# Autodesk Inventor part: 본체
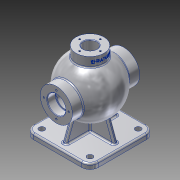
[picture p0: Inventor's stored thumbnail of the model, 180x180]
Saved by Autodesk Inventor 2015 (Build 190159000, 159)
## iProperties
Created: 2025-08
Part Number: 본체
Material: 알루미늄 6061
Document SubType Name: Modeling
Designer: USER
Density: 2.7 g/cm^3
Appearance: 알루미늄 - 평지
Author: USER
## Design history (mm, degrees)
sketch "스케치2"
  geometry: L1 (-46.5, -62.5)-(46.5, -62.5); L2 (62.5, -46.5)-(62.5, 46.5); L3 (46.5, 62.5)-(-46.5, 62.5); L4 (-62.5, 46.5)-(-62.5, -46.5); L5 (-62.5, -62.5)-(62.5, 62.5); L6 (62.5, -62.5)-(-62.5, 62.5); A1 r 16 centre (-46.5, 46.5) between (-46.5, 62.5) and (-62.5, 46.5); A2 r 16 centre (46.5, 46.5) between (62.5, 46.5) and (46.5, 62.5); A3 r 16 centre (46.5, -46.5) between (46.5, -62.5) and (62.5, -46.5); A4 r 16 centre (-46.5, -46.5) between (-62.5, -46.5) and (-46.5, -62.5); 1 further point
  constraints: 12 end point, 8 point on circle, 8 point on line, 8 tangent, 4 centre point, 3 equal radius, 2 midpoint, 2 parallel, 1 horizontal, 1 perpendicular
  dimensions: "d0" = 125 distance of L6.end L5.end; "d1" = 125 distance of L5.end L6.start; "d4" = 16 radius of A1
extrude "돌출1" new body sketch "스케치2" distance "d2" = 10; taper "d3" = 0 deg
sketch "스케치6"
  geometry: L1 (-46.5, 0)-(46.5, 0) reference; L2 (0, 139)-(0, 31); A1 r 54 centre (0, 85) between (0, 139) and (0, 31); 3 further points
  constraints: 2 end point, 2 midpoint, 2 point on circle, 1 centre point, 1 coincident, 1 vertical, 1 vertical alignment
  dimensions: "d20" = 108 diameter of A1; "d21" = 85 distance from line of A1.centre L1
revolve "회전1" sketch "스케치6" stored, may be unused: angle "d22" = 90 deg
node "작업 평면1"
sketch "스케치7"
  geometry: C1 r 27 at (0, 0); 1 further point
  constraints: 1 centre point, 1 coincident
  dimensions: "d24" = 54 diameter of C1
extrude "돌출2" join sketch "스케치7" stored distance "d25" = 10; taper "d26" = 0 deg
node "작업 평면2"
sketch "스케치8"
  geometry: C1 r 31 at (0, 83); 1 further point
  constraints: 1 centre point, 1 vertical alignment
  dimensions: "d28" = 62 diameter of C1; "d29" = 83 distance of point (0, 0) C1.centre
extrude "돌출3" join sketch "스케치8" distance "d30" = 130; taper "d31" = 0 deg
sketch "스케치9"
  geometry: L1 (-4, -50.5)-(4, -50.5); L2 (4, -50.5)-(4, 50.5); L3 (4, 50.5)-(-4, 50.5); L4 (-4, 50.5)-(-4, -50.5); L5 (-4, -50.5)-(4, 50.5); L6 (4, -50.5)-(-4, 50.5); L7 (-50.5, -4)-(50.5, -4); L8 (50.5, -4)-(50.5, 4); L9 (50.5, 4)-(-50.5, 4); L10 (-50.5, 4)-(-50.5, -4); L11 (-50.5, -4)-(50.5, 4); L12 (50.5, -4)-(-50.5, 4); L13 (-46.5, 62.5)-(46.5, 62.5) reference; L14 (62.5, 46.5)-(62.5, -46.5) reference; 1 further point
  constraints: 24 end point, 4 midpoint, 4 parallel, 2 horizontal, 2 perpendicular
  dimensions: "d32" = 8 distance of L2.end L3.end; "d33" = 8 distance of L7.end L8.end; "d34" = 12 distance between parallel lines of L3 L13; "d35" = 12 distance between parallel lines of L8 L14
extrude "돌출4" join sketch "스케치9" distance "d36" = 85; taper "d37" = 0 deg
feature "면 기울기1" dims angle "d38" = 20 deg
hole "구멍1" diameter "d41" = 26; stored, may be unused: countersink angle "d45" = 90 deg, drill point angle "d47" = 0 deg; dims "d39" = 10, "d40" = 10, "d42" = 6, "d43" = 4, "d44" = 2, "d46" = 100
hole "구멍2" diameter "d50" = 30; stored, may be unused: countersink angle "d54" = 90 deg, drill point angle "d56" = 0 deg; dims "d48" = 10, "d49" = 10, "d51" = 6, "d52" = 35, "d53" = 16, "d55" = 100
sketch "스케치10"
  geometry: L1 (-27, 131.765)-(-27, 150) reference; L2 (-27, 150)-(-13, 150) reference; L3 (-13, 150)-(-13, 98) reference; L4 (-13, 98)-(-49, 98) reference; L5 (-49, 98)-(-49, 100.5) reference; L6 (-49, 100.5)-(-65, 100.5) reference; L7 (-65, 100.5)-(-65, 114) reference; L8 (-65, 114)-(-45.552, 114) reference; L9 (45.552, 114)-(65, 114) reference; L10 (65, 114)-(65, 100.5) reference; L11 (65, 100.5)-(49, 100.5) reference; L12 (49, 100.5)-(49, 98) reference; L13 (49, 98)-(13, 98) reference; L14 (13, 98)-(13, 150) reference; L15 (13, 150)-(27, 150) reference; L16 (27, 150)-(27, 131.765) reference; L17 (-62.5, 0)-(-62.5, 10) reference; L18 (-62.5, 10)-(-50.5, 10) reference; L19 (-50.5, 10)-(-37.385, 46.034) reference; L20 (-42.743, 52)-(-65, 52) reference; L21 (-65, 52)-(-65, 65.5) reference; L22 (-65, 65.5)-(-49, 65.5) reference; L23 (-49, 65.5)-(-49, 68) reference; L24 (-49, 68)-(-13, 68) reference; L25 (-13, 68)-(-13, 50) reference; L26 (-13, 50)-(13, 50) reference; L27 (13, 50)-(13, 68) reference; L28 (13, 68)-(49, 68) reference; L29 (49, 68)-(49, 65.5) reference; L30 (49, 65.5)-(65, 65.5) reference; L31 (65, 65.5)-(65, 52) reference; L32 (65, 52)-(42.743, 52) reference; L33 (37.385, 46.034)-(50.5, 10) reference; L34 (50.5, 10)-(62.5, 10) reference; L35 (62.5, 10)-(62.5, 0) reference; L36 (62.5, 0)-(-62.5, 0) reference; L37 (-44, 85)-(44, 85); L38 (49, 98)-(49, 68) reference; A1 r 54 centre (0, 85) between (-27, 131.765) and (-45.552, 114) reference; A2 r 54 centre (0, 85) between (45.552, 114) and (27, 131.765) reference; A3 r 54 centre (0, 85) between (-42.743, 52) and (-37.385, 46.034) reference; A4 r 54 centre (0, 85) between (37.385, 46.034) and (42.743, 52) reference; A5 r 44 centre (0, 85) between (44, 85) and (-44, 85); 1 further point
  constraints: 2 end point, 2 point on circle, 1 centre point, 1 coincident, 1 midpoint, 1 perpendicular
  dimensions: "d57" = 88 diameter of A5
revolve "회전2" sketch "스케치10" stored, may be unused: angle "d58" = 90 deg
sketch "스케치11"
  geometry: 1 further point
sketch "스케치12"
  geometry: L1 (0, 0)-(20, 0)
  constraints: 2 end point, 1 horizontal
  dimensions: "d59" = 20 distance of L1.start L1.end
hole "구멍3" sketch "스케치12" at (20, 0) diameter "d60" = 3.242; stored, may be unused: countersink angle "d64" = 90 deg, drill point angle "d66" = 118 deg; dims "d61" = 12, "d62" = 35, "d63" = 16, "d65" = 15
sketch "스케치13"
  geometry: L1 (0, 0)-(0, 24); C1 r 17.5 at (0, 0) reference; C2 r 31 at (0, 0) reference; 1 further point
  constraints: 2 end point, 1 vertical
  dimensions: "d70" = 24 distance of L1.start L1.end
hole "구멍4" sketch "스케치13" at (0, 24) diameter "d71" = 3.242; stored, may be unused: countersink angle "d75" = 90 deg, drill point angle "d77" = 118 deg; dims "d72" = 12, "d73" = 35, "d74" = 16, "d76" = 15
sketch "스케치14"
  geometry: 1 further point
sketch "스케치15"
  geometry: L1 (-13, 150)-(13, 150) reference; 3 further points
  constraints: 1 midpoint, 1 vertical alignment, 1 other
  dimensions: "d81" = 9 distance from line of point (0, 141) L1
feature "엠보싱1" sketch "스케치15" dims "d0" = 125, "d1" = 125, "d4" = 16, "d20" = 108, "d21" = 85, "d82" = 0.5, "d83" = 0
chamfer "모따기1" distance "d84" = 1; stored, may be unused: second distance "d85" = 2, angle "d86" = 45 deg
fillet "모깎기1" dims "d87" = 0.6
fillet "모깎기2" dims "d88" = 3
fillet "모깎기3" dims "d89" = 3
fillet "모깎기4" dims "d90" = 3
hole "구멍5" diameter "d93" = 11; stored, may be unused: countersink angle "d97" = 90 deg, drill point angle "d99" = 0 deg; dims "d91" = 10, "d92" = 10, "d94" = 12, "d95" = 35, "d96" = 16, "d98" = 15
node "솔리드1"
mirror "대칭1"
pattern_circular "원형 패턴1" dims angle "d68" = 360 deg
pattern_circular "원형 패턴2" dims angle "d79" = 360 deg
mirror "대칭2"
pattern_linear "직사각형 패턴1" dims "d102" = 93, "d105" = 93
node "투영된 루프1"
node "절단 모서리 투영2"
other parameters: "d27" = -65
